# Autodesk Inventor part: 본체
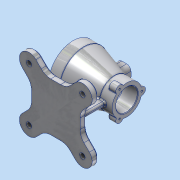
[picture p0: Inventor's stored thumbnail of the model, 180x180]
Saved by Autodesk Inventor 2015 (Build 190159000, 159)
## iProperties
Created: 2018-03
Part Number: 본체
Material: 알루미늄 6061
Document SubType Name: Modeling
Designer: SCD-A05
Density: 2.7 g/cm^3
Appearance: 알루미늄 - 평지
Mass: 1011.26 g
Surface Area: 853.881 cm^2
Volume: 374.54 cm^3
Author: SCD-A05
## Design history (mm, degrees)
sketch "스케치1"
  geometry: L1 (0, 0)-(100, 0); L2 (0, 35)-(0, 45); L3 (0, 45)-(20, 45); L4 (20, 45)-(77, 27.5); L5 (77, 27.5)-(100, 27.5); L6 (100, 27.5)-(100, 20); L7 (100, 20)-(70, 20); L8 (70, 20)-(70, 26); L9 (70, 26)-(23, 26); L10 (23, 26)-(23, 35); L11 (23, 35)-(0, 35); 2 further points
  constraints: 22 end point, 7 perpendicular, 2 midpoint, 2 vertical alignment, 1 horizontal, 1 parallel, 1 vertical
  dimensions: "d0" = 100 distance of L1.start L1.end; "d1" = 70 diameter of L11 L1; "d2" = 52 diameter of L9 L1; "d3" = 40 diameter of L7 L1; "d4" = 90 diameter of L3 L1; "d5" = 30 distance between parallel lines of L6 L8; "d6" = 47 distance between parallel lines of L10 L8; "d7" = 20 distance of L2.end L3.end; "d8" = 77 distance from line of L2 L4.end; "d9" = 55 diameter of L5 L1
revolve "회전1" sketch "스케치1" stored, may be unused: angle "d10" = 90 deg
sketch "스케치2"
  geometry: 2 further points
  constraints: 1 vertical alignment
  dimensions: "d11" = 40 distance of point (0, 0) point (0, 40)
hole "구멍1" sketch "스케치2" at (0, 40) diameter "d12" = 3.242; stored, may be unused: countersink angle "d16" = 90 deg, drill point angle "d18" = 118 deg; dims "d13" = 9, "d14" = 4, "d15" = 2, "d17" = 11
sketch "스케치3"
  geometry: C1 r 7 at (0, 27.5); C2 r 45 at (0, 0) reference; C3 r 7 at (-23.816, -13.75); C4 r 7 at (23.816, -13.75); 2 further points
  constraints: 3 centre point, 2 vertical alignment, 8 other
  dimensions: "d22" = 14 diameter of C1; "d25" = 360 deg dimension on C2.centre C1.centre (derived)
extrude "돌출1" join sketch "스케치3" distance "d27" = 15; taper "d28" = 0 deg
hole "구멍2" diameter "d31" = 3.242; stored, may be unused: countersink angle "d35" = 90 deg, drill point angle "d37" = 118 deg; dims "d29" = 10, "d30" = 10, "d32" = 9, "d33" = 4, "d34" = 2, "d36" = 11
hole "구멍3" diameter "d40" = 3.242; stored, may be unused: countersink angle "d44" = 90 deg, drill point angle "d46" = 118 deg; dims "d38" = 10, "d39" = 10, "d41" = 9, "d42" = 4, "d43" = 2, "d45" = 11
hole "구멍4" diameter "d49" = 3.242; stored, may be unused: countersink angle "d53" = 90 deg, drill point angle "d55" = 118 deg; dims "d47" = 10, "d48" = 10, "d50" = 9, "d51" = 4, "d52" = 2, "d54" = 11
node "작업 평면1"
sketch "스케치4"
  geometry: L1 (-37.5, 12.5)-(-62.5, 12.5); L2 (-62.5, 12.5)-(-62.5, -12.5); L3 (-62.5, -12.5)-(-37.5, -12.5); L4 (-37.5, -12.5)-(-37.5, 12.5); L5 (-50, -12.5)-(-50, 12.5); L6 (0, 45)-(0, -45) reference; 1 further point
  constraints: 10 end point, 2 midpoint, 2 parallel, 1 horizontal, 1 perpendicular
  dimensions: "d57" = 25 distance between parallel lines of L1 L3; "d58" = 25 distance between parallel lines of L2 L4; "d59" = 12.5 distance from line of point (0, 0) L3; "d60" = 50 distance between parallel lines of L6 L5
extrude "돌출2" join sketch "스케치4" stored distance "d61" = 10; taper "d62" = 0 deg
sketch "스케치5"
  geometry: L1 (-42.5, 7.5)-(-57.5, 7.5); L2 (-57.5, 7.5)-(-57.5, -7.5); L3 (-57.5, -7.5)-(-42.5, -7.5); L4 (-42.5, -7.5)-(-42.5, 7.5); L5 (-50, -7.5)-(-50, 7.5); L6 (0, 45)-(0, -45) reference; 1 further point
  constraints: 10 end point, 2 midpoint, 2 parallel, 1 horizontal, 1 perpendicular
  dimensions: "d63" = 15 distance of L3.end L2.end; "d64" = 15 distance of L2.end L1.end; "d65" = 50 distance between parallel lines of L6 L5; "d66" = 7.5 distance from line of point (0, 0) L3
extrude "돌출3" cut sketch "스케치5" distance "d67" = 27.25; taper "d68" = 0 deg
node "작업 평면2"
sketch "스케치6"
  geometry: L1 (-50, 0)-(-50, 77.225); L2 (-50, 0)-(-99.497, 49.497); L3 (-69.544, -45)-(-30.456, -45); L4 (-5, -19.544)-(-5, 19.544); L5 (-30.456, 45)-(-69.544, 45); L6 (-95, 19.544)-(-95, -19.544); L7 (-161.576, -111.576)-(-71.576, -21.576); L8 (61.576, -111.576)-(-161.576, 111.576); L9 (-50, 0)-(-36.63, 13.37); L10 (-50, 0)-(-51.605, 1.605); L11 (-50, 0)-(-179.348, -129.348); L12 (-13.23, 62.225)-(-30.456, 45); L13 (12.225, 36.77)-(-5, 19.544); L14 (-86.77, 62.225)-(-69.544, 45); L15 (-112.225, 36.77)-(-95, 19.544); L16 (-95, -19.544)-(-112.225, -36.77); L17 (-69.544, -45)-(-86.77, -62.225); L18 (-5, -19.544)-(12.225, -36.77); L19 (-30.456, -45)-(-13.23, -62.225); L20 (-50, 0)-(-50, 35.239); L21 (-50, 0)-(-202.697, 0); L22 (0, 45)-(0, -45) reference; A1 r 18 centre (-99.497, 49.497) between (-86.77, 62.225) and (-110.483, 35.239); A2 r 70 centre (-50, 0) between (-99.497, 49.497) and (-0.503, 49.497); A3 r 18 centre (-0.503, 49.497) between (12.225, 36.77) and (-13.23, 62.225); A4 r 18 centre (-0.503, -49.497) between (-13.23, -62.225) and (12.225, -36.77); A5 r 18 centre (-99.497, -49.497) between (-112.225, -36.77) and (-86.77, -62.225); 2 further points
  constraints: 42 end point, 14 point on circle, 10 parallel, 8 tangent, 5 centre point, 5 point on line, 3 midpoint, 2 horizontal, 1 horizontal alignment, 1 perpendicular, 1 vertical, 3 other
  dimensions: "d70" = 36 diameter of A1; "d71" = 140 diameter of A2; "d72" = 45 deg angle of L1 L2; "d73" = 90 distance between parallel lines of L6 L4; "d74" = 90 distance between parallel lines of L3 L5; "d75" = 18 radius of A3; "d76" = 45 deg angle of L1 L9; "d77" = 45 deg angle of L1 L11; "d78" = 45 deg angle of L1 L10; "d79" = 18 radius of A4; "d80" = 18 radius of A5; "d81" = 45 distance from line of L4 L1.start; "d82" = 45 distance from line of L3 L1.start; "d83" = 50 distance from line of L1.start L22
extrude "돌출4" join sketch "스케치6" distance "d84" = 12; taper "d85" = 0 deg
hole "구멍5" diameter "d88" = 10; stored, may be unused: countersink angle "d92" = 90 deg, drill point angle "d94" = 118 deg; dims "d86" = 10, "d87" = 10, "d89" = 6, "d90" = 4, "d91" = 2, "d93" = 8
hole "구멍6" diameter "d97" = 10; stored, may be unused: countersink angle "d101" = 90 deg, drill point angle "d103" = 118 deg; dims "d95" = 10, "d96" = 10, "d98" = 6, "d99" = 4, "d100" = 2, "d102" = 8
hole "구멍7" diameter "d106" = 10; stored, may be unused: countersink angle "d110" = 90 deg, drill point angle "d112" = 118 deg; dims "d104" = 10, "d105" = 10, "d107" = 6, "d108" = 4, "d109" = 2, "d111" = 8
hole "구멍8" diameter "d115" = 10; stored, may be unused: countersink angle "d119" = 90 deg, drill point angle "d121" = 118 deg; dims "d113" = 10, "d114" = 10, "d116" = 6, "d117" = 4, "d118" = 2, "d120" = 8
sketch "스케치7"
  geometry: L1 (87, -25)-(87, -70); L2 (30.456, -82)-(30.456, -70) reference; L3 (87, -70)-(13, -70); L4 (13, -70)-(13, -38); L5 (62.5, 45)-(37.5, 45) reference; L6 (50, 45)-(50, -184.319); L7 (13, -38)-(77, -25); L8 (77, -25)-(87, -25); L9 (77, -27.5)-(77, 27.5) reference; L10 (86.77, -70)-(69.544, -70) reference; 1 further point
  constraints: 12 end point, 3 perpendicular, 1 collinear, 1 midpoint, 1 parallel, 1 point on line, 1 vertical
  dimensions: "d122" = 37 distance between parallel lines of L6 L1; "d123" = 37 distance between parallel lines of L4 L6; "d126" = 45 distance between parallel lines of L3 L8; "d127" = 32 distance of L3.end L4.end
extrude "돌출5" join sketch "스케치7" stored distance "d124" = 8; taper "d125" = 0 deg
node "작업 평면3"
sketch "스케치8"
  geometry: L1 (-24, -70)-(-20.25, -27.137); L2 (-20.25, -27.137)-(20.25, -27.137); L3 (20.25, -27.137)-(24, -70); L4 (24, -70)-(-24, -70); L5 (19.544, -70)-(-19.544, -70) reference; L6 (67.497, -70)-(36.77, -70) reference; L7 (-36.77, -70)-(-67.497, -70) reference; 3 further points
  constraints: 8 end point, 1 collinear, 1 horizontal, 1 parallel
  dimensions: "d129" = 95 deg angle of L6 L3; "d130" = 95 deg angle of L7 L1; "d131" = 24 horizontal distance of point (0, 0) L1.start; "d132" = 24 horizontal distance of point (0, 0) L3.end; "d133" = 40.5 distance of L1.end L2.end
extrude "돌출6" join sketch "스케치8" stored distance "d134" = 8; taper "d135" = 0 deg
fillet "모깎기1" dims "d136" = 25
chamfer "모따기1" distance "d137" = 3; stored, may be unused: second distance "d138" = 2, angle "d139" = 45 deg
fillet "모깎기2" dims "d140" = 3
fillet "모깎기3" dims "d141" = 3
fillet "모깎기4" dims "d142" = 1
fillet "모깎기5" dims "d143" = 8
fillet "모깎기6" dims "d144" = 3
fillet "모깎기7" dims "d145" = 1
chamfer "모따기2" distance "d146" = 1; stored, may be unused: second distance "d147" = 2, angle "d148" = 45 deg
chamfer "모따기3" distance "d149" = 1; stored, may be unused: second distance "d150" = 2, angle "d151" = 45 deg
fillet "모깎기8" dims "d152" = 3
fillet "모깎기9" dims "d153" = 3
fillet "모깎기10" dims "d154" = 3
sketch "스케치9"
  geometry: L1 (33.408, -32.598)-(66.592, -32.598); L2 (66.592, -32.598)-(66.592, -37.402); L3 (66.592, -37.402)-(33.408, -37.402); L4 (33.408, -37.402)-(33.408, -32.598); L5 (33.408, -35)-(66.592, -35); L6 (50, -32.598)-(50, -37.402); L7 (95, -9.189)-(95, 9.189) reference; 1 further point
  constraints: 4 end point, 4 midpoint, 2 other
  dimensions: "d155" = 45 distance between parallel lines of L7 L6; "d157" = 35 distance from line of point (0, 0) L5
feature "엠보싱1" sketch "스케치9" dims "d0" = 100, "d1" = 70, "d2" = 52, "d3" = 40, "d4" = 90, "d5" = 30, "d6" = 47, "d7" = 20, "d8" = 77, "d9" = 55, "d158" = 0.5, "d159" = 0
node "솔리드1"
pattern_circular "원형 패턴1" dims angle "d20" = 360 deg
other parameters: "d56" = 45, "d69" = -82
